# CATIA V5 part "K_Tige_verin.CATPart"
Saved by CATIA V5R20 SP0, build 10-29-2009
Part number: Tige_verin
Bounding box of the stored display mesh (mm): x -10 to 10, y -6.546 to 13.514, z -5.258 to 162.975
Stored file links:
  G:\Khaled_CFAO_2011\SIL\SIL_GR2\zthiebault\Khaled\CAD_ThinkMOTION\K_Tige_verin.CATPart
  F:\Projet Thinkmotion\Catia\FINAL\HabillageFinal.CATProduct
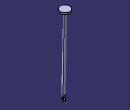
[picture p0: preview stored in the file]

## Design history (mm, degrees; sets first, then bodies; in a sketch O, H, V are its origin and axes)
Set1
  Plane1: linked copy from another document
  Plane2 "Plan_base_tige": linked copy from another document
  Line1 "Droite_base_tige1": linked copy from another document
  Plane3: linked copy from another document
  DatumCurve1: linked copy from another document
  DatumCurve2: linked copy from another document
  DatumSurface1: linked copy from another document
  Point1 "Point_base_tige1": linked copy from another document
  Point2 "Point_base_tige2": linked copy from another document
  DatumSurface2: linked copy from another document
Body1 (main body)
  Sketch1 on Plane1, origin (0, 0.0044, -0.0001), H (1, 0, 0), V (0, 0.0216, 0.9998)
    line L1 (0, 159.797) -> (3, 159.797)
    line L2 (3, 159.797) -> (3, -5.203)
    line L3 (3, -5.203) -> (0, -5.203)
    line L4 (0, -5.203) -> (0, 159.797)
    reference intersected line E1 through (0, 159.797) direction (-1, 0) from Plane2
    reference projected line E2 (0, -0.203) -> (0, 159.797) from Line1
    reference intersected line E3 through (0, -0.203) direction (-1, 0) from Plane3
    length L1 = 3
    distance E3 L3 = 5
    horizontal: L1 H, L3 H
    vertical: L2 V, L4 V
    coincidence: E1 L1, L4 E2
  Shaft1: profile Sketch1, axis Line1, angle 360
  Sketch2 on Plane1, origin (0, 0.0044, -0.0001), H (1, 0, 0), V (0, 0.0216, 0.9998)
    line L1 (-1.5, 5.9999) -> (1.5, 5.9999)
    line L2 (1.5, 5.9999) -> (1.5, -8.203)
    line L3 (1.5, -8.203) -> (-1.5, -8.203)
    line L4 (-1.5, -8.203) -> (-1.5, 5.9999)
    reference projected line E1 (-1.5, 0.1726) -> (-1.5, -14.8239) from edge of DatumCurve1
    reference projected line E2 (1.5, 0.1726) -> (1.5, -14.8239) from edge of DatumCurve2
    reference intersected line E3 (3, -5.203) -> (-3, -5.203) from face of Shaft1 from Sketch1.L3
    reference intersected line E4 (-1.5, 1.9999) -> (1.5, 1.9999) from face of DatumSurface1
    distance L3 E3 = 3
    distance L1 E4 = 4
    horizontal: L1 H, L3 H
    vertical: L2 V, L4 V
    coincidence: L4 E1, L2 E2
  Pocket1: profile Sketch2, direction (0, -0.9998, 0.0216), through (limit type 6), opposite side length 4
  Sketch3 on face of Shaft1 from Sketch1.L1, origin (0, 3.4474, 159.7599), H (-1, 0, 0), V (0, -0.9998, 0.0216)
    circle A1 centre (0, -0.0044) radius 10
    point P1 (0, -0.0044)
    reference projected point E1 (0, -0.0044) from Point1
    reference projected point E2 (5.547, 8.3161) from Point2
    coincidence: P1 E1, A1 E2
  Pad1: profile Sketch3, direction (0, 0.0216, 0.9998), length 3
  Sketch4 on face of DatumSurface2, origin (3.5, 0, -0.203), H (0, 1, 0), V (0, 0, 1)
    point P1 (0, 0)
    reference projected circle E1 centre (0, 0) radius 1.5 from edge of DatumSurface2
    concentricity: P1 E1
  Hole1: placed by Sketch4, at (3.5, 0, -0.203) direction (-1, 0, 0), diameter 3, depth 10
